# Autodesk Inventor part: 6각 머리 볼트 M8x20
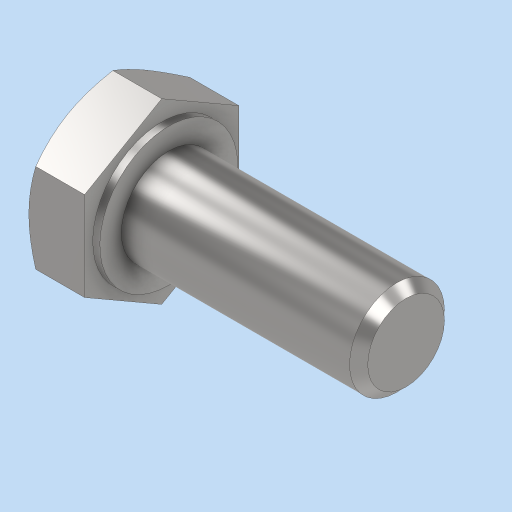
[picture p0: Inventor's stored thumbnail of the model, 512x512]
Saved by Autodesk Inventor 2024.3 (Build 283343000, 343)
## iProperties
Created: 2025-11
Part Number: 6각 머리 볼트 M8x20
Material: 강철, 연강
Description: 6각 머리 볼트 및 6각 머리 나사
Document SubType Name: Modeling
Designer: PC2-02
Density: 7.85 g/cm^3
Appearance: 기본값
Author: jhkim
Sending System: Autodesk Inventor 2026
Preprocessor: ST-DEVELOPER v20.1
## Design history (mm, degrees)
node "6각 머리 볼트 M8x201"
node "솔리드1"
body "Solid1"
